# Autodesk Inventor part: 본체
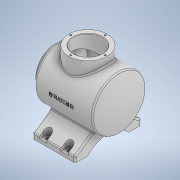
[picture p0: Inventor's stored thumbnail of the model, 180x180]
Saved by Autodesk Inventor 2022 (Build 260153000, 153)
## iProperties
Created: 2023-04
Part Number: 본체
Material: 일반
Document SubType Name: Modeling
Designer: Admin
Density: 1 g/cm^3
Appearance: 기본값
Author: Admin
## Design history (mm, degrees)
sketch "스케치2"
  geometry: L1 (0, -10.134)-(0, 60.805) reference; L2 (-38.908, 0)-(149.45, 0) reference; L3 (0, 0)-(108, 0); L4 (108, 0)-(108, 50); L5 (108, 50)-(0, 50); L6 (0, 50)-(0, 0); L7 (108, 0)-(119.664, 0); L8 (0, 0)-(-12, 0); L9 (-12, 0)-(-12, 36); L10 (-12, 36)-(0, 36); L11 (0, 36)-(0, 0); A1 r 113 centre (6.664, 0) between (119.664, 0) and (108, 50); 2 further points
  constraints: 18 end point, 4 parallel, 4 point on line, 2 horizontal, 2 perpendicular, 2 point on circle, 1 centre point, 1 collinear
  dimensions: "d0" = 100 diameter of L5 L2; "d1" = 108 distance of L4.end L5.end; "d2" = 113 radius of A1; "d3" = 12 distance of L9.end L10.end; "d4" = 72 diameter of L10 L2
revolve "회전1" sketch "스케치2" stored, may be unused: angle "d5" = 90 deg
node "작업 평면2"
sketch "스케치6"
  geometry: L1 (0, -144.515)-(0, 82.419) reference; L2 (-86.8, 0)-(86.8, 0) reference; L3 (-26.694, -42.278)-(-62, -67); L4 (-62, -67)-(-62, -77); L5 (-62, -77)-(-38.5, -77); L6 (-38.5, -77)-(0, -77); L7 (26.694, -42.278)-(62, -67); L8 (62, -67)-(62, -77); L9 (62, -77)-(38.5, -77); A1 r 52.096 centre (0, -112.096) between (0, -60) and (-38.5, -77); A2 r 52.096 centre (0, -112.096) between (38.5, -77) and (0, -60); 3 further points
  constraints: 14 end point, 4 point on circle, 4 symmetric about line, 3 point on line, 2 centre point, 2 perpendicular, 1 vertical, 3 other
  dimensions: "d26" = 10 distance of L3.end L4.end; "d27" = 38.5 distance from line of L1 L5.end; "d28" = 55 deg angle of L4 L3; "d29" = 77 distance between parallel lines of L5 L2; "d30" = 17 distance of L6.end A1.start; "d31" = 124 distance between parallel lines of L8 L4
extrude "돌출1" join sketch "스케치6" distance "d32" = 80; taper "d33" = 0 deg
node "작업 평면3"
sketch "스케치7"
  geometry: L1 (31.6, 0)-(-105.6, 0) reference; L2 (0, -50.4)-(0, 50.4) reference; L3 (12, 36)-(12, -36) reference; C1 r 36 at (-50, 0); 1 further point
  constraints: 1 centre point, 1 point on line
  dimensions: "d36" = 72 diameter of C1; "d38" = 62 distance from line of C1.centre L3
extrude "돌출2" join sketch "스케치7" stored distance "d39" = 10; taper "d40" = 0 deg
sketch "스케치8"
  geometry: C1 r 36 at (0, 0) reference; C2 r 27 at (0, 0); 1 further point
  constraints: 1 centre point, 1 coincident
  dimensions: "d41" = 54 diameter of C2
extrude "돌출3" cut sketch "스케치8" distance "d42" = 65; taper "d43" = 0 deg
sketch "스케치9" dims "d77" = 3
  geometry: L1 (-38.333, 0)-(145.997, 0) reference; L2 (-12, -36)-(-12, 36) reference; L3 (-12, 0)-(7, 0); L4 (7, 0)-(7, 27); L5 (7, 27)-(-12, 27); L6 (-12, 27)-(-12, 0); L7 (7, 0)-(103.876, 0); L8 (103.55, 43)-(7, 43); L9 (7, 43)-(7, 0); L10 (103.876, 0)-(113.757, 0); A1 r 113 centre (6.664, 0) between (108, -50) and (108, 50) reference; A2 r 106 centre (6.664, 0) between (112.664, 0) and (103.55, 43); 4 further points
  constraints: 16 end point, 3 parallel, 2 horizontal, 2 point on circle, 2 point on line, 1 centre point, 1 midpoint, 1 perpendicular
  dimensions: "d44" = 7 radial gap between concentric circles of A1 A2; "d45" = 86 diameter of L8 L1; "d46" = 19 distance of L4.end L5.end; "d47" = 54 diameter of L5 L1
revolve "회전2" sketch "스케치9" stored, may be unused: angle "d48" = 90 deg
node "작업 평면5"
sketch "스케치11"
  geometry: L1 (0, 23.5)-(80, 23.5) reference; L2 (0, 0)-(0, 23.5) reference; L3 (13, 15.5)-(27, 15.5); L4 (27, 15.5)-(27, 23.5); L5 (27, 23.5)-(13, 23.5); L6 (13, 23.5)-(13, 15.5); L7 (53, 15.5)-(67, 15.5); L8 (67, 15.5)-(67, 23.5); L9 (67, 23.5)-(53, 23.5); L10 (53, 23.5)-(53, 15.5); L11 (-46.333, -38.5)-(137.997, -38.5) reference; L12 (27, -100.5)-(13, -100.5); L13 (27, -92.5)-(27, -100.5); L14 (13, -100.5)-(13, -92.5); L15 (53, -100.5)-(53, -92.5); L16 (67, -100.5)-(53, -100.5); L17 (67, -92.5)-(67, -100.5); A1 r 7 centre (20, 15.5) between (13, 15.5) and (27, 15.5); A2 r 7 centre (60, 15.5) between (53, 15.5) and (67, 15.5); A3 r 7 centre (20, -92.5) between (27, -92.5) and (13, -92.5); A4 r 7 centre (60, -92.5) between (67, -92.5) and (53, -92.5); 1 further point
  constraints: 28 end point, 10 symmetric about line, 8 point on circle, 4 centre point, 4 parallel, 2 horizontal, 2 midpoint, 2 perpendicular, 2 point on line, 2 other
  dimensions: "d59" = 14 distance of L3.start L3.end; "d60" = 20 distance from line of A1.centre L2; "d61" = 8 distance from line of L1 A1.centre; "d62" = 14 distance of L7.start L7.end; "d63" = 40 distance of A2.centre A1.centre; "d64" = 8 distance between parallel lines of L1 L7
extrude "돌출4" cut sketch "스케치11" distance "d65" = 20; taper "d66" = 0 deg
sketch "스케치12"
  geometry: A1 r 7 centre (20, -15.5) between (27, -15.5) and (13, -15.5) reference; A2 r 7 centre (60, -15.5) between (67, -15.5) and (53, -15.5) reference; A3 r 7 centre (20, 92.5) between (13, 92.5) and (27, 92.5) reference; A4 r 7 centre (60, 92.5) between (53, 92.5) and (67, 92.5) reference; 5 further points
  constraints: 4 coincident
hole "구멍1" sketch "스케치12" at (20, -15.5), (60, -15.5), (20, 92.5), (60, 92.5) diameter "d67" = 6; stored, may be unused: countersink angle "d71" = 90 deg, drill point angle "d73" = 118 deg; dims "d68" = 9, "d69" = 4, "d70" = 2, "d72" = 6
fillet "모깎기1" dims "d74" = 3
fillet "모깎기2" dims "d75" = 3
fillet "모깎기3" dims "d76" = 3
fillet "모깎기4" dims "d77" = 3
sketch "스케치13" dims "d78" = 65
  geometry: L1 (0, 93.4)-(0, -105.4) reference; 6 further points
  constraints: 1 coincident, 1 point on line, 1 vertical alignment, 7 other
  dimensions: "d81" = 360 deg dimension on point (0, 0) point (0, -32.5) (derived)
hole "구멍2" sketch "스케치13" at (0, -32.5), (32.5, 0), (0, 32.5), (-32.5, 0) diameter "d83" = 3.242; stored, may be unused: countersink angle "d87" = 90 deg, drill point angle "d89" = 118 deg; dims "d84" = 8, "d85" = 4, "d86" = 2, "d88" = 10
sketch "스케치14" dims "d90" = 65
  geometry: L1 (-88.333, 0)-(95.997, 0) reference; C1 r 27 at (0, 0) reference; 6 further points
  constraints: 1 coincident, 1 horizontal alignment, 1 point on line, 7 other
  dimensions: "d93" = 360 deg dimension on point (0, 0) point (-32.5, 0) (derived)
hole "구멍3" sketch "스케치14" at (-32.5, 0), (0, -32.5), (32.5, 0), (0, 32.5) diameter "d95" = 3.242; stored, may be unused: countersink angle "d99" = 90 deg, drill point angle "d101" = 118 deg; dims "d96" = 8, "d97" = 4, "d98" = 2, "d100" = 10
chamfer "모따기1" distance "d102" = 1; stored, may be unused: second distance "d103" = 2, angle "d104" = 45 deg
chamfer "모따기2" distance "d105" = 1; stored, may be unused: second distance "d106" = 2, angle "d107" = 45 deg
fillet "모깎기5" dims "d108" = 3
node "작업 평면6"
sketch "스케치15"
  geometry: L1 (-12, -36)-(-12, 36) reference; L2 (-38.333, 0)-(145.997, 0) reference; 2 further points
  constraints: 1 other
  dimensions: "d110" = 62 distance from line of point (50, 0) L1; "d111" = 0 distance from line of L2 point (50, 0)
feature "엠보싱1" sketch "스케치15" dims "d26" = 10, "d27" = 38.5, "d28" = 55 deg, "d29" = 77, "d30" = 17, "d31" = 124, "d112" = 0.5, "d113" = 0
node "솔리드1"
feature "A9D066F2-1C7D-4E18-AEED-F7BC21143FA4" dims "d67" = 6, "d68" = 9, "d69" = 4, "d70" = 2, "d71" = 90 deg, "d72" = 6, "d73" = 118 deg
other parameters: "d34" = 65, "d54" = -6, "d109" = 125
